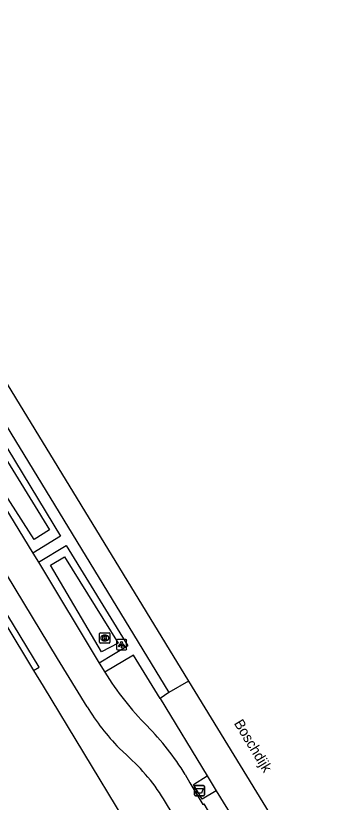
# Model space of a CAD drawing. Extents: x 159888 to 160757, y 384031 to 384746.
# Drawn here: x 160410.5 to 160441.7, y 384646.9 to 384723.6 of the extents above; entities that cross this region are included whole.
import ezdxf

# ---------------------------------------------------------------- set-up
doc = ezdxf.new("R2010")
doc.units = 0
for name, color, linetype in [('IMGEO_Afval_apart_plaats', 7, 'Continuous'), ('IMGEO_Fietspad_gesloten', 7, 'Continuous'), ('IMGEO_Kolk', 7, 'Continuous'), ('IMGEO_Lichtpunt', 7, 'Continuous'), ('IMGEO_Openbare_ruimte_label', 7, 'Continuous'), ('IMGEO_Pand', 7, 'Continuous'), ('IMGEO_Rijbaan_lokaal_gesloten', 7, 'Continuous'), ('IMGEO_Voetpad_gesloten', 7, 'Continuous'), ('IMGEO_Voetpad_onverhard', 7, 'Continuous'), ('IMGEO_Voetpad_open', 7, 'Continuous'), ('IMGEO_Waterloop', 7, 'Continuous')]:
    doc.layers.add(name, color=color, linetype=linetype)

msp = doc.modelspace()

# ---------------------------------------------------------------- linework, layer by layer
at = {"layer": 'IMGEO_Afval_apart_plaats'}
for p, q in [((160427.892, 384647.644), (160427.892, 384648.444)), ((160427.892, 384648.444), (160427.892, 384647.644)), ((160427.992, 384648.544), (160428.782, 384648.544)), ((160428.782, 384648.544), (160427.992, 384648.544)), ((160428.882, 384648.444), (160428.882, 384647.644)), ((160428.882, 384647.644), (160428.882, 384648.444)), ((160428.782, 384647.544), (160427.992, 384647.544)), ((160427.992, 384647.544), (160428.782, 384647.544))]:
    msp.add_line(p, q, dxfattribs=at)
msp.add_lwpolyline([(160428.035, 384648.258), (160428.739, 384648.258), (160428.59, 384647.788), (160428.184, 384647.788), (160428.035, 384648.258)], dxfattribs=at)
for centre, start, end in [((160427.992, 384648.444), 90, 180), ((160427.992, 384648.444), 90, 180), ((160428.782, 384648.444), 0, 90), ((160428.782, 384648.444), 360, 90), ((160427.992, 384647.644), 180, 270), ((160427.992, 384647.644), 180, 270), ((160428.782, 384647.644), 270, 0), ((160428.782, 384647.644), 270, 0)]:
    msp.add_arc(centre, 0.1, start, end, dxfattribs=at)
at = {"layer": 'IMGEO_Fietspad_gesloten'}
for points in [[(160417.417, 384656.218), (160414.548, 384660.916), (160399.665, 384685.458), (160394.225, 384694.244), (160376.446, 384723.648)], [(160406.182, 384680.943), (160412.126, 384671.197)], [(160412.126, 384671.197), (160412.678, 384670.329)], [(160412.678, 384670.329), (160418.585, 384660.487)], [(160418.585, 384660.487), (160419.153, 384659.582)], [(160421.287, 384651.487), (160420.537, 384652.191)], [(160427.003, 384649.617), (160427.434, 384648.786), (160428.701, 384646.685), (160428.817, 384646.742), (160432.1, 384641.147), (160432.486, 384640.562)], [(160441.736, 384619.457), (160425.084, 384646.903)]]:
    msp.add_lwpolyline(points, dxfattribs=at)
for centre, radius, start, end in [((160445.393, 384676.003), 30.955, 212.0378, 224.38684), ((160438.229, 384669.12), 24.487, 211.79675, 223.73818), ((160404.684, 384635.86), 26.218, 31.64859, 44.84847), ((160408.35, 384636.906), 19.493, 30.85311, 48.41787)]:
    msp.add_arc(centre, radius, start, end, dxfattribs=at)
at = {"layer": 'IMGEO_Kolk'}
for p, q in [((160418.649, 384662.509), (160418.649, 384663.361)), ((160418.724, 384663.435), (160419.576, 384663.435)), ((160419.137, 384663.215), (160419.162, 384663.215)), ((160419.65, 384663.361), (160419.65, 384662.509)), ((160419.576, 384662.435), (160418.724, 384662.435)), ((160419.16, 384662.655), (160419.135, 384662.655))]:
    msp.add_line(p, q, dxfattribs=at)
for points in [[(160418.649, 384662.509), (160418.649, 384663.361)], [(160418.724, 384663.435), (160419.576, 384663.435)], [(160418.97, 384663.135), (160419.093, 384663.135), (160419.093, 384662.984), (160419.223, 384663.135), (160419.387, 384663.135), (160419.241, 384662.984), (160419.394, 384662.735), (160419.242, 384662.735), (160419.157, 384662.899), (160419.093, 384662.832), (160419.093, 384662.735), (160418.97, 384662.735), (160418.97, 384663.135)], [(160419.65, 384663.361), (160419.65, 384662.509)], [(160419.576, 384662.435), (160418.724, 384662.435)]]:
    msp.add_lwpolyline(points, dxfattribs=at)
for centre, start, end in [((160418.726, 384663.359), 91.55205, 178.44795), ((160418.726, 384663.359), 91.55205, 178.44795), ((160419.574, 384663.359), 1.55205, 88.44795), ((160419.574, 384663.359), 1.55205, 88.44795), ((160418.726, 384662.511), 181.55205, 268.44795), ((160418.726, 384662.511), 181.55205, 268.44795), ((160419.574, 384662.511), 271.55205, 358.44795), ((160419.574, 384662.511), 271.55205, 358.44795)]:
    msp.add_arc(centre, 0.0765, start, end, dxfattribs=at)
for centre, major_axis, ratio, start_param, end_param in [((160419.136, 384662.935), (-0.387, 0.002), 0.722429, 4.712389, 7.853982), ((160419.161, 384662.935), (-0.39, 0.002), 0.717154, 1.570796, 4.712389)]:
    msp.add_ellipse(centre, major_axis=major_axis, ratio=ratio, start_param=start_param, end_param=end_param, dxfattribs=at)
at = {"layer": 'IMGEO_Lichtpunt'}
for p, q in [((160420.288, 384662.693), (160420.288, 384661.886)), ((160420.288, 384662.693), (160420.288, 384661.886)), ((160421.19, 384662.788), (160420.382, 384662.788)), ((160421.19, 384662.788), (160420.382, 384662.788)), ((160421.284, 384661.886), (160421.284, 384662.693)), ((160421.284, 384661.886), (160421.284, 384662.693)), ((160420.382, 384661.792), (160421.19, 384661.792)), ((160420.382, 384661.792), (160421.19, 384661.792))]:
    msp.add_line(p, q, dxfattribs=at)
for points in [[(160420.662, 384662.357), (160420.701, 384662.329), (160420.513, 384662.067), (160420.475, 384662.094), (160420.662, 384662.357)], [(160420.764, 384662.309), (160420.811, 384662.309), (160420.811, 384661.987), (160420.764, 384661.987), (160420.764, 384662.309)], [(160420.874, 384662.329), (160420.912, 384662.356), (160421.099, 384662.094), (160421.06, 384662.066), (160420.874, 384662.329)]]:
    msp.add_lwpolyline(points, dxfattribs=at)
msp.add_circle((160420.787, 384662.491), 0.0994, dxfattribs=at)
for centre, start, end in [((160420.382, 384662.693), 90, 180), ((160420.382, 384662.693), 90, 180), ((160421.19, 384662.693), 0, 90), ((160421.19, 384662.693), 0, 90), ((160420.382, 384661.886), 180, 270), ((160420.382, 384661.886), 180, 270), ((160421.19, 384661.886), 270, 0), ((160421.19, 384661.886), 270, 360)]:
    msp.add_arc(centre, 0.0946, start, end, dxfattribs=at)
at = {"layer": 'IMGEO_Pand'}
for points in [[(160392.576, 384692.166), (160395.491, 384687.374), (160403.96, 384673.388), (160412.203, 384659.764)], [(160412.203, 384659.764), (160413.13, 384658.232), (160421.024, 384645.221), (160421.028, 384645.215), (160419.246, 384644.139), (160424.95, 384634.77)]]:
    msp.add_lwpolyline(points, dxfattribs=at)
at = {"layer": 'IMGEO_Rijbaan_lokaal_gesloten'}
for points in [[(160407.539, 384691.037), (160408.168, 384690.032), (160427.305, 384658.73)], [(160427.305, 384658.73), (160436.779, 384643.259)]]:
    msp.add_lwpolyline(points, dxfattribs=at)
at = {"layer": 'IMGEO_Voetpad_gesloten'}
for points in [[(160430.03, 384648.017), (160428.657, 384647.197), (160427.8, 384648.65), (160429.145, 384649.471)], [(160429.145, 384649.471), (160430.03, 384648.017)]]:
    msp.add_lwpolyline(points, dxfattribs=at)
at = {"layer": 'IMGEO_Voetpad_onverhard'}
for points in [[(160427.305, 384658.73), (160425.411, 384657.617)], [(160424.543, 384657.031), (160429.145, 384649.471)], [(160430.03, 384648.017), (160434.025, 384641.532)]]:
    msp.add_lwpolyline(points, dxfattribs=at)
at = {"layer": 'IMGEO_Voetpad_open'}
for points in [[(160412.203, 384659.764), (160412.748, 384660.084), (160393.061, 384692.471), (160392.576, 384692.166)], [(160405.69, 384689.924), (160425.411, 384657.617)], [(160406.182, 384680.943), (160408.939, 384682.59), (160414.84, 384672.858), (160412.126, 384671.197)], [(160412.678, 384670.329), (160415.383, 384671.955), (160421.406, 384662.158), (160418.585, 384660.487)], [(160424.543, 384657.031), (160421.946, 384661.268), (160419.153, 384659.582)], [(160425.411, 384657.617), (160424.543, 384657.031)]]:
    msp.add_lwpolyline(points, dxfattribs=at)
at = {"layer": 'IMGEO_Waterloop'}
for points in [[(160407.088, 384680.584), (160408.748, 384681.59), (160413.74, 384673.496), (160412.265, 384672.542), (160407.088, 384680.584)], [(160418.823, 384661.583), (160413.858, 384670.048), (160415.208, 384670.858), (160420.47, 384662.428), (160418.823, 384661.583)]]:
    msp.add_lwpolyline(points, dxfattribs=at)

# ---------------------------------------------------------------- texts
at = {"layer": 'IMGEO_Openbare_ruimte_label'}
msp.add_text('Boschdijk', height=1, rotation=301.1308, dxfattribs=at).set_placement((160431.721, 384654.614))

doc.saveas('drawing.dxf')
